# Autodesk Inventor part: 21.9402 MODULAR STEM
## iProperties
Created: 2010-10
Part Number: 21.9402 MODULAR STEM
Document SubType Name: Modeling
Designer: Administrator
Density: 7.85 g/cm^3
Material: Steel
Mass: 28.6962 g
Surface Area: 25.5066 cm^2
Volume: 3.65557 cm^3
Author: Administrator
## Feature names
1. Base1
2. Extrusion1
